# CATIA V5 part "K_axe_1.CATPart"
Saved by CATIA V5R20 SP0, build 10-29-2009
Part number: axe 1
Publications: "Droite.2", "Plan.2"
Bounding box of the stored display mesh (mm): x -160 to 160, y -20 to 20, z -19.993 to 19.993
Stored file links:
  G:\Khaled_CFAO_2011\ST2M\ST2M_GR1\mponsin\Khaled\CAD_ThinkMOTION\K_axe_1.CATPart
  C:\Users\Socar\Documents\thinkmotion\Final\Diff2.CATProduct
  C:\Users\Socar\Desktop\CFAO\axe 2.CATPart
  G:\Khaled_CFAO_2011\ST2M\ST2M_GR1\mponsin\Khaled\CAD_ThinkMOTION\K_mponsin.CATProduct
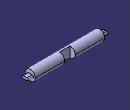
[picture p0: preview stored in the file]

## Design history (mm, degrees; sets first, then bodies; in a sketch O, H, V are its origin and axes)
External parameters (linked from other documents)
  `External.R interne` = 160 mm
  `External.D axe` = 40 mm
  External.Rmeplat = 5 mm
  External.Lmeplat = 25 mm
Set1
  Line1 "axe general": linked copy from another document
  Point1 "Origine": linked copy from another document
  Plane1: linked copy from another document
Set2
  Line2: type PtDir, RefPoint Point1, Direction yz-plane, Start 0, End 20
  Plane2: type 1Curve, Element1 edge [face of Pocket2 from Sketch3.A3 | start face of Pad1]
Body1 (main body)
  Sketch1 on yz-plane, origin (0, 0, 0), H (0, 1, 0), V (0, 0, 1)
    circle A1 centre (0, 0) radius 20
    radius A1 = 20 {= `External.D axe` /2}
  Pad1: profile Sketch1, direction (1, 0, 0), length 160 {= `External.R interne`}, opposite side length 160 {= `External.R interne`}
  Sketch2 on xy-plane, origin (0, 0, 0), H (1, 0, 0), V (0, 1, 0)
    line L1 (21, 24) -> (-21, 24)
    line L2 (-21, 24) -> (-21, -1)
    line L3 (-21, -1) -> (21, -1)
    line L4 (21, -1) -> (21, 24)
    distance L3 H = 1
    length L1 = 42 {= 2mm+`External.D axe`}
    length L4 = 25 {= 5mm+`External.D axe` /2}
    horizontal: L1 H, L3 H
    vertical: L2 V, L4 V
    symmetry: L4 L2 V
  Pocket1: profile Sketch2, direction (0, 0, -1), through (limit type 6), opposite side through (limit type 6)
  Sketch3 on start face of Pad1, origin (-160, 0, 0), H (0, -1, 0), V (0, 0, 1)
    line L1 (0, 5) -> (-7.5, 5)
    point P1 (0, 5)
    point P2 (-7.5, 5)
    arc A1 centre (-7.5, 0) radius 5 from (-7.5, 5) to (-12.5, 0) ccw
    point P3 (-7.5, 0)
    point P4 (-12.5, 0)
    point P5 (-7.5, -5)
    point P6 (0, -5)
    line L2 (0, -5) -> (-7.5, -5)
    point P7 (-12.5, 0)
    arc A2 centre (-7.5, 0) radius 5 from (-7.5, -5) to (-12.5, 0) cw
    point P9 (7.5, 5)
    point P10 (0, 5)
    line L3 (0, 5) -> (7.5, 5)
    point P11 (7.5, -5)
    point P12 (0, -5)
    line L4 (0, -5) -> (7.5, -5)
    point P13 (12.5, 0)
    arc A3 centre (7.5, 0) radius 5 from (7.5, -5) to (12.5, 0) ccw
    point P15 (12.5, 0)
    arc A4 centre (7.5, 0) radius 5 from (7.5, 5) to (12.5, 0) cw
    circle A5 centre (0, 0) radius 23
    radius A1 = 5 {= External.Rmeplat}
    distance A4 A1 = 25 {= External.Lmeplat}
    radius A5 = 23 {= 3mm+`External.D axe` /2}
    coincidence: P1 V, P3 H, P4 H, P1 P10, P4 P7, P6 P12, P13 P15
    horizontal: L1 H
    tangency: A1 L1
    symmetry: P2 P5 H, P1 P6 H, L1 L2 H, P4 P7 H, A1 A2 H, P2 P9 V, P1 P10 V, L1 L3 V, P5 P11 V, P6 P12 V, L2 L4 V, P7 P13 V, A2 A3 V, P4 P15 V, A1 A4 V
  Pocket2: profile Sketch3, direction (1, 0, 0), up to Plane1
  CircPattern1: of Pocket2, instances 2, angular step 180, axis from Line1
